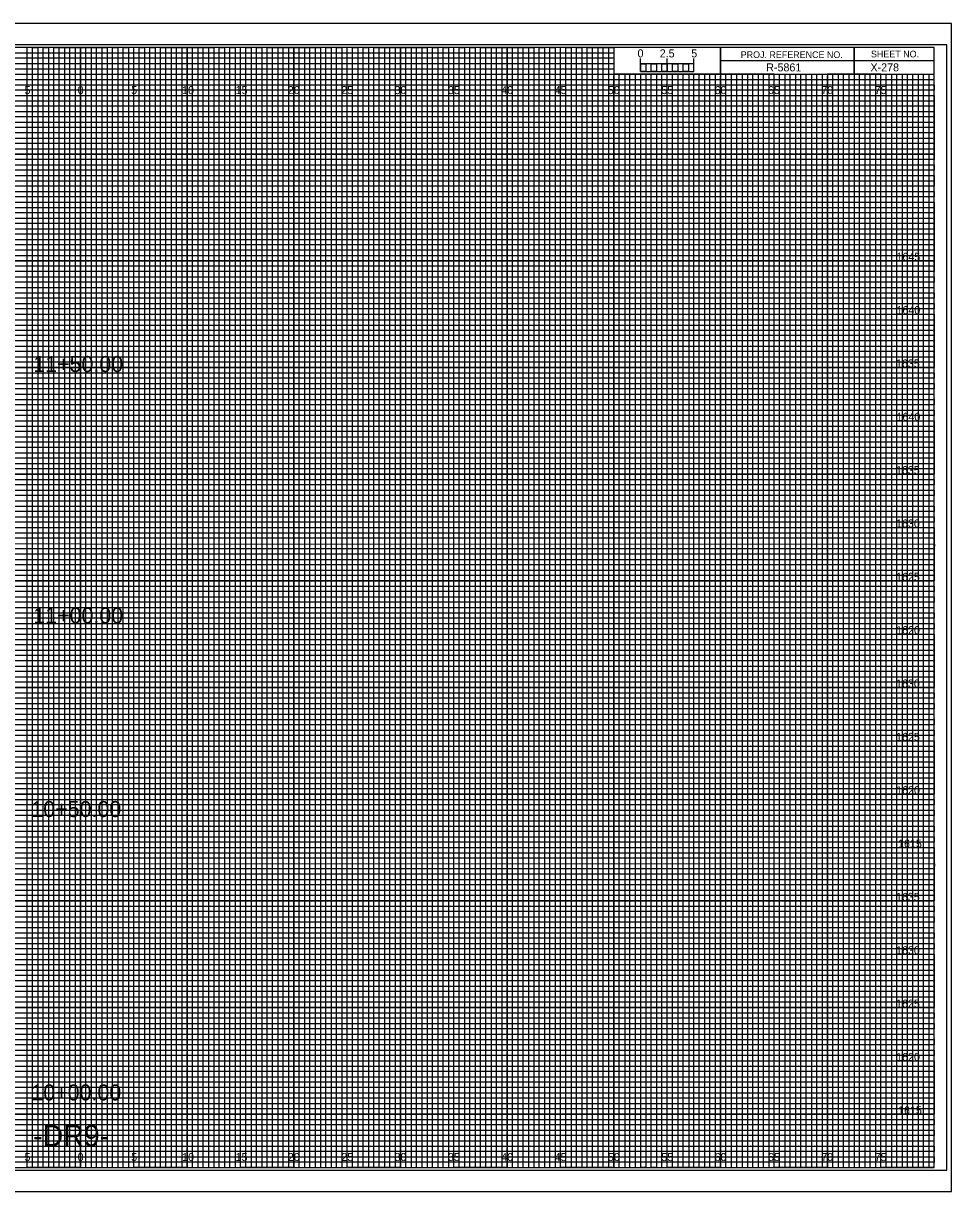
# Model space of a CAD drawing. Extents: x -7 to 162, y -2 to 107.
# Drawn here: x 74.6 to 161.7, y -2.3 to 107.3 of the extents above; entities that cross this region are included whole.
import ezdxf

# ---------------------------------------------------------------- set-up
doc = ezdxf.new("R2010")
doc.units = 0
for name, color, linetype in [('Prop XS Alignment Label', 7, 'Continuous'), ('Prop XS Bar Scale Labels', 7, 'Continuous'), ('Prop XS Elevation Labels', 7, 'Continuous'), ('Prop XS Offset Labels', 7, 'Continuous'), ('Prop XS Project Number', 7, 'Continuous'), ('Prop XS Sheet Number', 7, 'Continuous'), ('Prop XS Station Labels', 7, 'Continuous'), ('Sheet Cross Section CELL', 7, 'Continuous'), ('Sheet Cross Section Grid Major CELL', 7, 'Continuous'), ('Sheet Cross Section Grid Middle CELL', 7, 'Continuous'), ('Sheet Cross Section Grid Minor 1 CELL', 7, 'Continuous'), ('Sheet Cross Section Grid Minor 2 CELL', 7, 'Continuous'), ('Sheet Cross Section Scale CELL', 7, 'Continuous'), ('Sheet Cutting Line CELL', 7, 'Continuous'), ('Sheet DOT Grid CELL', 7, 'Continuous'), ('Sheet Plot Border Inside CELL', 7, 'Continuous'), ('Sheet Plot Border Outside CELL', 7, 'Continuous')]:
    doc.layers.add(name, color=color, linetype=linetype)

msp = doc.modelspace()

# ---------------------------------------------------------------- linework, layer by layer
at = {"layer": 'Sheet Cross Section CELL'}
for p, q in [((152.5, 105), (152.5, 102.5)), ((152.5, 102.5), (152.5, 105)), ((160, 103.75), (140, 103.75)), ((140, 103.75), (140, 102.5)), ((140, 102.5), (160, 102.5))]:
    msp.add_line(p, q, dxfattribs=at)
for points in [[(160, 105), (0, 105), (0, 0), (160, 0)], [(140, 105), (130, 105), (130, 102.52), (140, 102.52)], [(160, 105), (140, 105), (140, 102.5), (160, 102.5)]]:
    msp.add_lwpolyline(points, close=True, dxfattribs=at)
at = {"layer": 'Sheet Cross Section Grid Major CELL'}
for p, q in [((75, 105), (70, 105)), ((75, 0), (75, 105)), ((85, 105), (80, 105)), ((80, 105), (80, 0)), ((85, 0), (85, 105)), ((95, 105), (90, 105)), ((90, 105), (90, 0)), ((95, 0), (95, 105)), ((105, 105), (100, 105)), ((100, 105), (100, 0)), ((105, 0), (105, 105)), ((115, 105), (110, 105)), ((110, 105), (110, 0)), ((115, 0), (115, 105)), ((125, 105), (120, 105)), ((120, 105), (120, 0)), ((125, 0), (125, 105)), ((130, 105), (130, 0)), ((135, 0), (135, 102.5)), ((145, 102.5), (140, 102.5)), ((140, 102.5), (140, 0)), ((145, 0), (145, 102.5)), ((155, 102.5), (150, 102.5)), ((150, 102.5), (150, 0)), ((155, 0), (155, 102.5)), ((80, 0), (75, 0)), ((90, 0), (85, 0)), ((100, 0), (95, 0)), ((110, 0), (105, 0)), ((120, 0), (115, 0)), ((130, 0), (125, 0)), ((140, 0), (135, 0)), ((150, 0), (145, 0)), ((160, 0), (155, 0)), ((160, 0), (160, 0))]:
    msp.add_line(p, q, dxfattribs=at)
for points in [[(0, 100), (160, 100), (160, 95), (0, 95)], [(0, 90), (160, 90), (160, 85), (0, 85)], [(0, 80), (160, 80), (160, 75), (0, 75)], [(0, 70), (160, 70), (160, 65), (0, 65)], [(0, 60), (160, 60), (160, 55), (0, 55)], [(0, 50), (160, 50), (160, 45), (0, 45)], [(0, 40), (160, 40), (160, 35), (0, 35)], [(0, 30), (160, 30), (160, 25), (0, 25)], [(0, 20), (160, 20), (160, 15), (0, 15)], [(0, 10), (160, 10), (160, 5), (0, 5)]]:
    msp.add_lwpolyline(points, dxfattribs=at)
at = {"layer": 'Sheet Cross Section Grid Middle CELL'}
for points in [[(72.5, 0), (77.5, 0), (77.5, 105), (82.5, 105), (82.5, 0), (87.5, 0), (87.5, 105), (92.5, 105), (92.5, 0), (97.5, 0), (97.5, 105), (102.5, 105), (102.5, 0), (107.5, 0), (107.5, 105), (112.5, 105), (112.5, 0), (117.5, 0), (117.5, 105), (122.5, 105), (122.5, 0), (127.5, 0), (127.5, 105), (129.97, 105), (130, 105), (130, 102.5), (132.5, 102.5), (132.5, 0), (137.5, 0), (137.5, 102.5), (142.5, 102.5), (142.5, 0), (147.5, 0), (147.5, 102.5), (152.5, 102.5), (152.5, 0), (157.5, 0), (157.5, 102.5)], [(0, 102.5), (137.5, 102.5)], [(0, 92.5), (160, 92.5), (160, 97.5), (0, 97.5)], [(0, 82.5), (160, 82.5), (160, 87.5), (0, 87.5)], [(0, 72.5), (160, 72.5), (160, 77.5), (0, 77.5)], [(0, 62.5), (160, 62.5), (160, 67.5), (0, 67.5)], [(0, 52.5), (160, 52.5), (160, 57.5), (0, 57.5)], [(0, 42.5), (160, 42.5), (160, 47.5), (0, 47.5)], [(0, 32.5), (160, 32.5), (160, 37.5), (0, 37.5)], [(0, 22.5), (160, 22.5), (160, 27.5), (0, 27.5)], [(0, 12.5), (160, 12.5), (160, 17.5), (0, 17.5)], [(0, 2.5), (160, 2.5), (160, 7.5), (0, 7.5)]]:
    msp.add_lwpolyline(points, dxfattribs=at)
at = {"layer": 'Sheet Cross Section Grid Minor 1 CELL'}
for p, q in [((0, 104.5), (130, 104.5)), ((130, 104.5), (130, 103.99)), ((130, 103.99), (0, 103.99)), ((0, 103.5), (130, 103.5)), ((130, 102.95), (0, 102.95)), ((130, 103.5), (130, 102.95)), ((0, 102), (160, 102))]:
    msp.add_line(p, q, dxfattribs=at)
for points in [[(0, 101.5), (135, 101.5), (160, 101.5), (160, 101), (0, 101)], [(0, 100.5), (160, 100.5), (160, 99.5), (0, 99.5)], [(0, 99), (160, 99), (160, 98.5), (0, 98.49)], [(0, 98), (160, 98), (160, 97), (0, 97)], [(0, 96.5), (160, 96.5), (160, 96), (0, 96)], [(0, 95.5), (160, 95.5), (160, 94.5), (0, 94.5)], [(0, 94), (160, 94), (160, 93.5), (0, 93.5)], [(0, 93), (160, 93), (160, 92), (0, 92)], [(0, 91.5), (160, 91.5), (160, 91), (0, 91)], [(0, 90.5), (160, 90.5), (160, 89.5), (0, 89.5)], [(0, 89), (160, 89), (160, 88.5), (0, 88.5)], [(0, 88), (160, 88), (160, 86.98), (160, 86.5), (160, 86), (0, 86)], [(0, 87), (160, 87), (160, 86.5), (0, 86.5)], [(0, 85.5), (160, 85.5), (160, 84.5), (0, 84.52)], [(0, 84.52), (160, 84.5), (160, 84), (0, 84)], [(0, 83.5), (160, 83.5), (160, 83), (0, 83)], [(0, 82), (160, 82), (160, 81.5), (0, 81.5)], [(0, 81), (160, 81), (160, 80.5), (0, 80.5)], [(-0.04, 79.45), (160, 79.45), (160, 78.94), (-0.04, 78.94)], [(0, 78.5), (160, 78.5), (160, 78), (0, 78)], [(0, 77), (160, 77), (160, 76.5), (0, 76.5)], [(0, 76), (160, 76), (160, 75.5), (0, 75.5)], [(0, 74.5), (160, 74.5), (160, 74), (0, 74)], [(0, 73.5), (160, 73.5), (160, 73), (0, 73)], [(0, 72), (160, 72), (160, 71.5), (0, 71.5)], [(0, 71), (160, 71), (160, 70.5), (0, 70.5)], [(0, 69.5), (160, 69.5), (160, 68.99), (0, 69)], [(0, 68.5), (160, 68.5), (160, 68), (0, 68)], [(0, 67), (160, 67), (160, 66.5), (0, 66.5)], [(0, 66), (160, 66), (160, 65.5), (0, 65.5)], [(0, 64.5), (160, 64.5), (160, 64), (0, 64)], [(0, 63.5), (160, 63.5), (160, 63), (0, 63)], [(0, 62), (160, 62), (160, 61.5), (0, 61.5)], [(0, 61), (160, 61), (160, 60.5), (0, 60.5)], [(0, 59.5), (160, 59.5), (160, 59), (0, 59)], [(0, 58.5), (160.03, 58.45), (160, 58), (0, 58)], [(0, 57), (160, 57), (160, 56.5), (0, 56.5)], [(0, 56), (160, 56), (160, 55.5), (0, 55.5)], [(0, 54.5), (160, 54.5), (160, 54), (0, 54)], [(0, 53.5), (160, 53.5), (160, 53), (0, 53)], [(0, 52), (160, 52), (160, 51.5), (0, 51.5)], [(0, 51), (160, 51), (160, 50.5), (0, 50.5)], [(0, 49.5), (160, 49.5), (160, 49), (0, 49)], [(0, 48.5), (160, 48.5), (160, 48), (0, 48)], [(0, 47), (160, 47), (160, 46.5), (0, 46.5)], [(0, 46), (160, 46), (160, 45.5), (0, 45.5)], [(0, 44.5), (160, 44.5), (160, 44), (0, 44)], [(0, 43.5), (160, 43.5), (160, 43), (0, 43)], [(0, 42), (160, 42), (160, 41.5), (0, 41.5)], [(0, 41), (160, 41), (160, 40.5), (0, 40.5)], [(0, 39.5), (160, 39.5), (160, 38.99), (0, 39)], [(0, 38.5), (160, 38.5), (160, 38), (0, 38)], [(0, 37), (160, 37), (160, 36.5), (0, 36.5)], [(0, 36), (160, 36), (160, 35.5), (0, 35.5)], [(0, 34.5), (160, 34.5), (160, 34), (0, 34)], [(0, 33.5), (160, 33.5), (160, 33), (0, 33)], [(0, 32), (160, 32), (160, 31.5), (0, 31.5)], [(0, 31), (160, 31), (160, 30.5), (0, 30.5)], [(0, 29.5), (160, 29.5), (160, 29), (0, 29)], [(0, 28.5), (160.03, 28.46), (160, 28), (0, 28)], [(0, 27), (160, 27), (160, 26.5), (0, 26.5)], [(0, 26), (160, 26), (160, 25.5), (0, 25.5)], [(0, 24.5), (160, 24.5), (160, 24), (0, 24)], [(0, 23.5), (160, 23.5), (160, 23), (0, 23)], [(0, 22), (160, 22), (160, 21.5), (0, 21.5)], [(0, 21), (160, 21), (160, 20.5), (0, 20.5)], [(0, 19.5), (160, 19.5), (160, 19), (0, 19)], [(0, 18.5), (160, 18.5), (160, 18), (0, 18)], [(0, 17), (160, 17), (160, 16.5), (0, 16.5)], [(0, 16), (160, 16), (160, 15.5), (0, 15.5)], [(0, 14.5), (160, 14.5), (160, 14), (0, 14)], [(0, 13.5), (160, 13.5), (160, 13), (0, 13)], [(0, 12), (160, 12), (160, 11.5), (0, 11.5)], [(0, 11), (160, 11), (160, 10.5), (0, 10.5)], [(0, 9.5), (160, 9.5), (160, 9), (0, 9)], [(0, 8.5), (160, 8.5), (160, 8), (0, 8)], [(0, 7), (160, 7), (160, 6.5), (0, 6.5)], [(0, 6), (160, 6), (160, 5.5), (0, 5.5)], [(0, 4.5), (160, 4.5), (160, 4), (0, 4)], [(0, 3.5), (160, 3.5), (160, 3), (0, 3)], [(0, 2), (160, 2), (160, 1.5), (0, 1.5)], [(0, 1), (160, 1), (160, 0.5), (0, 0.5)]]:
    msp.add_lwpolyline(points, dxfattribs=at)
at = {"layer": 'Sheet Cross Section Grid Minor 2 CELL'}
for p, q in [((133.5, 102.5), (133, 102.5)), ((133, 102.5), (133, 0)), ((133.5, 0), (133.5, 102.5)), ((134.5, 102.5), (134, 102.5)), ((134, 102.5), (134, 0)), ((134.5, 0), (134.5, 102.5)), ((133, 0), (132.5, 0)), ((134, 0), (133.5, 0))]:
    msp.add_line(p, q, dxfattribs=at)
for points in [[(75, 0), (75.5, 0), (75.5, 105), (76, 105), (76, 0)], [(76, 0), (76.5, 0), (76.5, 105), (77, 105), (77, 0)], [(77.5, 0), (78, 0), (78, 105), (78.5, 105), (78.5, 0)], [(78.5, 0), (79, 0), (79, 105), (79.5, 105), (79.5, 0)], [(80, 0), (80.5, 0), (80.5, 105), (81, 105), (81, 0)], [(81, 0), (81.5, 0), (81.5, 105), (82, 105), (82, 0)], [(82.5, 0), (83, 0), (83, 105), (83.5, 105), (83.5, 0)], [(83.5, 0), (84, 0), (84, 105), (84.5, 105), (84.5, 0)], [(85, 0), (85.5, 0), (85.5, 105), (86, 105), (86, 0)], [(86, 0), (86.5, 0), (86.5, 105), (87, 105), (87, 0)], [(87.5, 0), (88, 0), (88, 105), (88.5, 105), (88.5, 0)], [(88.5, 0), (89, 0), (89, 105), (89.5, 105), (89.5, 0)], [(90, 0), (90.5, 0), (90.5, 105), (91, 105), (91, 0)], [(91, 0), (91.5, 0), (91.5, 105), (92, 105), (92, 0)], [(92.5, 0), (93, 0), (93, 105), (93.5, 105), (93.5, 0)], [(93.5, 0), (94, 0), (94, 105), (94.5, 105), (94.5, 0)], [(95, 0), (95.5, 0), (95.5, 105), (96, 105), (96, 0)], [(96, 0), (96.5, 0), (96.5, 105), (97, 105), (97, 0)], [(97.5, 0), (98, 0), (98, 105), (98.5, 105), (98.5, 0)], [(98.5, 0), (99, 0), (99, 105), (99.5, 105), (99.5, 0)], [(100, 0), (100.5, 0), (100.5, 105), (101, 105), (101, 0)], [(101, 0), (101.5, 0), (101.5, 105), (102, 105), (102, 0)], [(102.5, 0), (103, 0), (103, 105), (103.5, 105), (103.5, 0)], [(103.5, 0), (104, 0), (104, 105), (104.5, 105), (104.5, 0)], [(105, 0), (105.5, 0), (105.5, 105), (106, 105), (106, 0)], [(106, 0), (106.5, 0), (106.5, 105), (107, 105), (107, 0)], [(107.5, 0), (108, 0), (108, 105), (108.5, 105), (108.5, 0)], [(108.5, 0), (109, 0), (109, 105), (109.5, 105), (109.5, 0)], [(110, 0), (110.5, 0), (110.5, 105), (111, 105), (111, 0)], [(111, 0), (111.5, 0), (111.5, 105), (112, 105), (112, 0)], [(112.5, 0), (113, 0), (113, 105), (113.5, 105), (113.5, 0)], [(113.5, 0), (114, 0), (114, 105), (114.5, 105), (114.5, 0)], [(115, 0), (115.5, 0), (115.5, 105), (116, 105), (116, 0)], [(116, 0), (116.5, 0), (116.5, 105), (117, 105), (117, 0)], [(117.5, 0), (118, 0), (118, 105), (118.5, 105), (118.5, 0)], [(118.5, 0), (119, 0), (119, 105), (119.5, 105), (119.5, 0)], [(120, 0), (120.5, 0), (120.5, 105), (121, 105), (121, 0)], [(121, 0), (121.5, 0), (121.5, 105), (122, 105), (122, 0)], [(122.5, 0), (123, 0), (123, 105), (123.5, 105), (123.5, 0)], [(123.5, 0), (124, 0), (124, 105), (124.5, 105), (124.5, 0)], [(125, 0), (125.5, 0), (125.5, 105), (126, 105), (126, 0)], [(126, 0), (126.5, 0), (126.5, 105), (127, 105), (127, 0)], [(127.5, 0), (128, 0), (128, 105), (128.5, 105), (128.5, 0)], [(128.5, 0), (129, 0), (129, 105), (129.5, 105), (129.5, 0)], [(130, 0), (130.5, 0), (130.5, 102.5), (131.01, 102.5), (131.01, 0)], [(131, 0), (131.5, 0), (131.5, 102.5), (132, 102.5), (132, 0)], [(135, 0), (135.49, 0), (135.49, 102.5), (136, 102.5), (136, 0)], [(136, 0), (136.5, 0), (136.5, 102.5), (137.03, 102.5), (137.03, 0)], [(137.5, 0), (138, 0), (138, 102.5), (138.5, 102.5), (138.5, 0)], [(138.5, 0), (139, 0), (139, 102.5), (139.5, 102.5), (139.5, 0)], [(140, 0), (140.5, 0), (140.5, 102.5), (141, 102.5), (141, 0)], [(141, 0), (141.5, 0), (141.5, 102.5), (142, 102.5), (142, 0)], [(142.5, 0), (143, 0), (143, 102.5), (143.5, 102.5), (143.5, 0)], [(143.5, 0), (144, 0), (144, 102.5), (144.5, 102.5), (144.5, 0)], [(145, 0), (145.5, 0), (145.5, 102.5), (146, 102.5), (146, 0)], [(146, 0), (146.5, 0), (146.5, 102.5), (147, 102.5), (147, 0)], [(147.5, 0), (148, 0), (148, 102.5), (148.5, 102.5), (148.5, 0)], [(148.5, 0), (149, 0), (149, 102.5), (149.5, 102.5), (149.5, 0)], [(150, 0), (150.5, 0), (150.5, 102.5), (151, 102.5), (151, 0)], [(151, 0), (151.5, 0), (151.5, 102.5), (152, 102.5), (152, 0)], [(152.5, 0), (153, 0), (153, 102.5), (153.5, 102.5), (153.5, 0)], [(153.5, 0), (154, 0), (154, 102.5), (154.5, 102.5), (154.5, 0)], [(155, 0), (155.5, 0), (155.5, 102.5), (156, 102.5), (156, 0)], [(156, 0), (156.5, 0), (156.5, 102.5), (157, 102.5), (157, 0)], [(157.5, 0), (158, 0), (158, 102.5), (158.5, 102.5), (158.5, 0)], [(158.5, 0), (159, 0), (159, 102.5), (159.5, 102.5), (159.5, 0)]]:
    msp.add_lwpolyline(points, dxfattribs=at)
at = {"layer": 'Sheet Cross Section Scale CELL'}
for p, q in [((132.5, 102.75), (132.5, 103.95)), ((132.5, 103.45), (132.5, 103.95)), ((135, 102.75), (135, 103.95)), ((137.5, 102.75), (137.5, 103.95)), ((137.5, 103.45), (137.5, 103.95))]:
    msp.add_line(p, q, dxfattribs=at)
for points in [[(137.5, 103.45), (132.5, 103.45), (132.5, 102.75), (137.5, 102.75)], [(132.5, 103.45), (133, 103.45), (133, 102.75), (132.5, 102.75)], [(133.5, 103.45), (134, 103.45), (134, 102.75), (133.5, 102.75)], [(134.5, 103.45), (135, 103.45), (135, 102.75), (134.5, 102.75)], [(135.5, 103.45), (136, 103.45), (136, 102.75), (135.5, 102.75)], [(136.5, 103.45), (137, 103.45), (137, 102.75), (136.5, 102.75)]]:
    msp.add_lwpolyline(points, close=True, dxfattribs=at)
at = {"layer": 'Sheet Cutting Line CELL'}
for p, q in [((161.65, 107.25), (-6.7, 107.25)), ((-6.7, -2.25), (161.65, -2.25))]:
    msp.add_line(p, q, dxfattribs=at)
at = {"layer": 'Sheet DOT Grid CELL'}
for p, q in [((75, 0), (75, 105)), ((80, 0), (80, 105)), ((85, 0), (85, 105)), ((90, 0), (90, 105)), ((95, 0), (95, 105)), ((100, 0), (100, 105)), ((105, 0), (105, 105)), ((110, 0), (110, 105)), ((115, 0), (115, 105)), ((120, 0), (120, 105)), ((125, 0), (125, 105)), ((130, 0), (130, 102.34)), ((135, 0), (135, 102.34)), ((140, 0), (140, 102.34)), ((145, 0), (145, 102.34)), ((150, 0), (150, 102.34)), ((155, 0), (155, 102.34)), ((0, 100), (160, 100)), ((0, 95), (160, 95)), ((0, 90), (160, 90)), ((0, 85), (160, 85)), ((0, 80), (160, 80)), ((0, 75), (160, 75)), ((0, 70), (160, 70)), ((0, 65), (160, 65)), ((0, 60), (160, 60)), ((0, 55), (160, 55)), ((0, 50), (160, 50)), ((0, 45), (160, 45)), ((0, 40), (160, 40)), ((0, 35), (160, 35)), ((0, 30), (160, 30)), ((0, 25), (160, 25)), ((0, 20), (160, 20)), ((0, 15), (160, 15)), ((0, 10), (160, 10)), ((0, 5), (160, 5))]:
    msp.add_line(p, q, dxfattribs=at)
at = {"layer": 'Sheet Plot Border Inside CELL'}
msp.add_lwpolyline([(-5.4, -0.25), (161.2, -0.25), (161.2, 105.25), (-5.4, 105.25)], close=True, dxfattribs=at)
at = {"layer": 'Sheet Plot Border Outside CELL'}
msp.add_lwpolyline([(-6.7, -2.25), (161.65, -2.25), (161.65, 107.25), (-6.7, 107.25)], close=True, dxfattribs=at)

# ---------------------------------------------------------------- texts
at = {"layer": 'Prop XS Alignment Label'}
msp.add_text('-DR9-', height=2, dxfattribs=at).set_placement((75.55, 2))
at = {"layer": 'Prop XS Bar Scale Labels'}
for s, p in [('2.5', (134.29, 104.06)), ('5', (137.24, 104.06))]:
    msp.add_text(s, height=0.75, dxfattribs=at).set_placement(p)
at = {"layer": 'Prop XS Elevation Labels'}
for s, p in [('1645', (156.48, 85)), ('1640', (156.48, 80)), ('1635', (156.43, 75)), ('1640', (156.48, 70)), ('1635', (156.43, 65)), ('1630', (156.44, 60)), ('1625', (156.44, 55)), ('1620', (156.45, 50)), ('1630', (156.44, 45)), ('1625', (156.44, 40)), ('1620', (156.45, 35)), ('1615', (156.63, 30)), ('1635', (156.43, 25)), ('1630', (156.44, 20)), ('1625', (156.44, 15)), ('1620', (156.45, 10)), ('1615', (156.63, 5))]:
    msp.add_text(s, height=0.75, dxfattribs=at).set_placement(p)
at = {"layer": 'Prop XS Offset Labels'}
for s, p in [('5', (74.74, 100.62)), ('0', (79.73, 100.62)), ('0', (79.73, 100.62)), ('5', (84.74, 100.62)), ('10', (89.52, 100.62)), ('15', (94.53, 100.62)), ('20', (99.43, 100.62)), ('25', (104.44, 100.62)), ('30', (109.43, 100.62)), ('35', (114.44, 100.62)), ('40', (119.43, 100.62)), ('45', (124.44, 100.62)), ('50', (129.43, 100.62)), ('55', (134.44, 100.62)), ('60', (139.43, 100.62)), ('65', (144.44, 100.62)), ('70', (149.43, 100.62)), ('75', (154.44, 100.62)), ('5', (74.74, 0.62)), ('0', (79.73, 0.62)), ('0', (79.73, 0.62)), ('5', (84.74, 0.62)), ('10', (89.52, 0.62)), ('15', (94.53, 0.62)), ('20', (99.43, 0.62)), ('25', (104.44, 0.62)), ('30', (109.43, 0.62)), ('35', (114.44, 0.62)), ('40', (119.43, 0.62)), ('45', (124.44, 0.62)), ('50', (129.43, 0.62)), ('55', (134.44, 0.62)), ('60', (139.43, 0.62)), ('65', (144.44, 0.62)), ('70', (149.43, 0.62)), ('75', (154.44, 0.62))]:
    msp.add_text(s, height=0.75, dxfattribs=at).set_placement(p)
at = {"layer": 'Prop XS Project Number'}
msp.add_text('R-5861', height=0.75, dxfattribs=at).set_placement((144.27, 102.75))
at = {"layer": 'Prop XS Sheet Number'}
msp.add_text('X-278', height=0.75, dxfattribs=at).set_placement((154.04, 102.75))
at = {"layer": 'Prop XS Station Labels'}
for s, p in [('11+50.00', (75.57, 74.57)), ('11+00.00', (75.57, 51.01)), ('10+50.00', (75.39, 32.86)), ('10+00.00', (75.39, 6.3))]:
    msp.add_text(s, height=1.5, dxfattribs=at).set_placement(p)
at = {"layer": 'Sheet Cross Section CELL'}
for s, p in [('PROJ. REFERENCE NO.', (141.88, 104)), ('SHEET NO.', (154.09, 104.06))]:
    msp.add_text(s, height=0.625, dxfattribs=at).set_placement(p)
at = {"layer": 'Sheet Cross Section Scale CELL'}
msp.add_text('0', height=0.75, dxfattribs=at).set_placement((132.21, 104.06))

doc.saveas('drawing.dxf')
